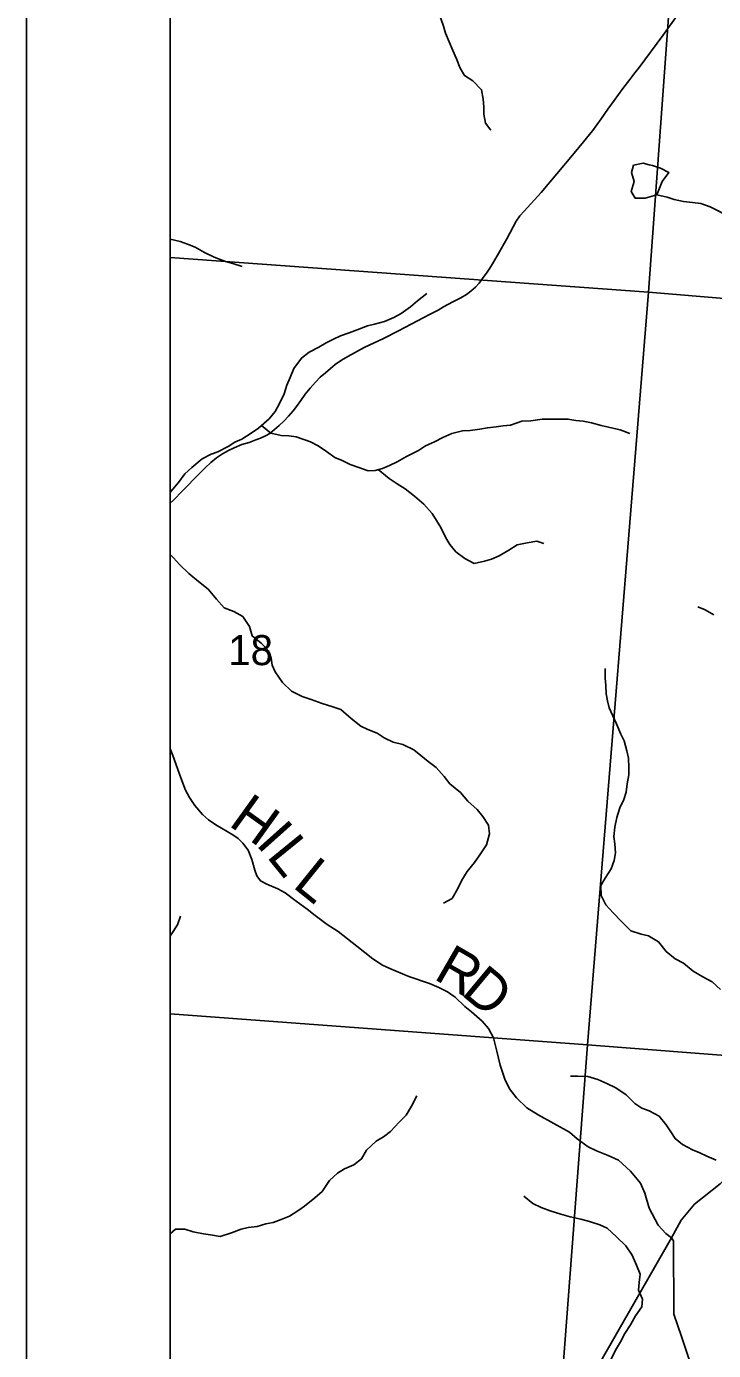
# Model space of a CAD drawing. Extents: x 0 to 42, y 0 to 22.
# Drawn here: x 2 to 2.478, y 14.957 to 15.878 of the extents above; entities that cross this region are included whole.
import ezdxf

# ---------------------------------------------------------------- set-up
doc = ezdxf.new("R2010")
doc.units = 0
for name, color, linetype in [('GM_X_Minor_Lake', 7, 'Continuous'), ('GM_X_Minor_River', 7, 'Continuous'), ('GM_X_Section', 7, 'Continuous'), ('GM_X_Section_Text', 7, 'Continuous'), ('GM_X_State_Route', 7, 'Continuous'), ('GM_X_Township_Road', 7, 'Continuous'), ('GM_X_Township_Road_Text', 7, 'Continuous'), ('GM_X_Unincorporated', 7, 'Continuous'), ('SH_Cut_Line', 7, 'Continuous'), ('SH_Data', 7, 'Continuous')]:
    doc.layers.add(name, color=color, linetype=linetype)

msp = doc.modelspace()

# ---------------------------------------------------------------- linework, layer by layer
at = {"layer": 'GM_X_Minor_Lake'}
for points in [[(2.43328, 15.78219), (2.42907, 15.78317), (2.42245, 15.78187), (2.4211, 15.77676), (2.42297, 15.7705), (2.42087, 15.76368), (2.4235, 15.75893), (2.4305, 15.75891), (2.43864, 15.76115)], [(2.43864, 15.76115), (2.44245, 15.77061), (2.44702, 15.77685), (2.44116, 15.7799), (2.43569, 15.78163), (2.43328, 15.78219)]]:
    msp.add_lwpolyline(points, dxfattribs=at)
at = {"layer": 'GM_X_Minor_River'}
for points in [[(2.27116, 15.92349), (2.27428, 15.9183), (2.27766, 15.91185), (2.28047, 15.90502), (2.28291, 15.89856), (2.28609, 15.89078), (2.28834, 15.88395), (2.29021, 15.87864), (2.29171, 15.87371), (2.29677, 15.86175), (2.29921, 15.85586), (2.30183, 15.84941), (2.30484, 15.84428), (2.31069, 15.84066), (2.31672, 15.83438), (2.31783, 15.82794), (2.31819, 15.82244), (2.31836, 15.81732), (2.31947, 15.81106), (2.32323, 15.80631)], [(2.5144, 15.73699), (2.5093, 15.7389), (2.50382, 15.74119), (2.49815, 15.74292), (2.49324, 15.74408), (2.48833, 15.74618), (2.48267, 15.74942), (2.47568, 15.75286), (2.46926, 15.75516), (2.46359, 15.75594), (2.45716, 15.75672), (2.45073, 15.75807), (2.44582, 15.75961), (2.43864, 15.76115)], [(2.1, 15.73038), (2.10694, 15.72866), (2.11204, 15.72694), (2.11733, 15.72483), (2.12393, 15.72121), (2.13054, 15.71777), (2.13847, 15.7149), (2.14358, 15.71355), (2.15019, 15.71144)], [(2.1, 15.55412), (2.10043, 15.55471), (2.10575, 15.56094), (2.11031, 15.56718), (2.11506, 15.57152), (2.12227, 15.57756), (2.12852, 15.58076), (2.13326, 15.58245), (2.14027, 15.58621), (2.14501, 15.58903), (2.14993, 15.59129), (2.15638, 15.59544), (2.1615, 15.59883), (2.1689, 15.60543), (2.17308, 15.61034), (2.17613, 15.61602), (2.17937, 15.62264), (2.18128, 15.62889), (2.18357, 15.63419), (2.18605, 15.64043), (2.19138, 15.64761), (2.19669, 15.65176), (2.20351, 15.65534), (2.20863, 15.65835), (2.21356, 15.6608), (2.21848, 15.66305), (2.22454, 15.66511), (2.23003, 15.66718), (2.23723, 15.66999), (2.24216, 15.6713), (2.24916, 15.67317), (2.2556, 15.6758), (2.26072, 15.67862), (2.26736, 15.68333), (2.2721, 15.68749), (2.27855, 15.69258)], [(2.1636, 15.6007), (2.17, 15.59539), (2.17718, 15.59365), (2.18247, 15.59344), (2.18777, 15.59285), (2.19759, 15.58941), (2.20307, 15.58654), (2.20873, 15.58254), (2.21457, 15.57835), (2.21967, 15.57625), (2.22534, 15.57357), (2.23119, 15.57147), (2.23781, 15.56917), (2.24272, 15.56934), (2.24765, 15.57084), (2.25257, 15.5729), (2.25788, 15.57535), (2.26451, 15.57911), (2.27285, 15.58325), (2.27778, 15.58645), (2.28384, 15.58946), (2.28972, 15.59247), (2.29597, 15.5951), (2.30354, 15.59697), (2.30884, 15.59714), (2.31546, 15.59806), (2.32077, 15.59918), (2.32682, 15.59972), (2.33174, 15.60046), (2.33685, 15.60101), (2.34461, 15.60364), (2.35105, 15.60399), (2.35881, 15.6051), (2.37148, 15.60505), (2.37678, 15.60522), (2.38226, 15.60425), (2.38736, 15.60367), (2.39322, 15.60251), (2.40002, 15.60077), (2.41325, 15.59769), (2.41986, 15.5952)], [(2.24484, 15.56998), (2.25235, 15.56381), (2.25801, 15.56018), (2.26348, 15.55656), (2.27009, 15.55161), (2.2765, 15.5459), (2.28234, 15.53944), (2.28534, 15.53469), (2.28835, 15.52975), (2.29192, 15.52253), (2.29455, 15.51778), (2.29888, 15.51284), (2.30511, 15.50808), (2.31153, 15.50464), (2.31872, 15.50632), (2.32364, 15.50763), (2.32895, 15.51007), (2.33558, 15.51403), (2.34146, 15.51761), (2.34846, 15.5191), (2.35509, 15.52021), (2.36, 15.51848)], [(2.1, 15.51086), (2.10234, 15.50865), (2.10648, 15.50389), (2.11308, 15.49781), (2.11968, 15.4921), (2.12647, 15.48676), (2.13231, 15.47992), (2.13758, 15.47383), (2.14438, 15.47116), (2.15061, 15.46772), (2.15512, 15.46088), (2.15699, 15.45424), (2.16322, 15.44929), (2.16849, 15.44396), (2.17018, 15.43884), (2.17091, 15.43391), (2.17317, 15.42916), (2.17825, 15.42175), (2.18447, 15.41586), (2.19183, 15.41204), (2.19806, 15.40993), (2.20581, 15.40725), (2.21318, 15.40495), (2.21884, 15.40303), (2.22601, 15.39675), (2.23261, 15.39142), (2.23752, 15.38912), (2.24394, 15.38664), (2.24885, 15.38339), (2.25527, 15.38034), (2.26188, 15.3788), (2.26962, 15.37498), (2.27452, 15.37098), (2.27962, 15.36679), (2.28509, 15.3626), (2.29074, 15.35651), (2.29469, 15.35138), (2.30205, 15.34529), (2.30713, 15.33921), (2.31373, 15.3335), (2.31749, 15.32855), (2.32163, 15.32266), (2.32218, 15.3166), (2.32007, 15.30883), (2.3155, 15.30184), (2.31189, 15.29655), (2.30676, 15.29031), (2.30296, 15.28426), (2.3001, 15.27858), (2.29629, 15.27159), (2.29022, 15.26839)], [(2.47841, 15.46895), (2.47237, 15.47238), (2.46727, 15.47449)], [(2.48293, 15.20815), (2.47709, 15.21347), (2.47067, 15.2171), (2.46407, 15.22092), (2.45728, 15.22663), (2.45143, 15.22949), (2.4452, 15.23463), (2.43993, 15.24148), (2.43295, 15.24548), (2.42766, 15.24664), (2.42067, 15.24913), (2.41388, 15.25579), (2.40823, 15.2615), (2.40314, 15.2672), (2.39995, 15.27366), (2.3996, 15.28048), (2.40264, 15.28559), (2.40683, 15.29221), (2.40893, 15.29788), (2.4099, 15.30338), (2.40954, 15.30963), (2.4088, 15.31475), (2.40939, 15.32119), (2.41074, 15.32801), (2.41304, 15.33464), (2.41571, 15.34031), (2.41724, 15.34561), (2.41802, 15.35129), (2.41918, 15.35755), (2.41919, 15.36266), (2.41884, 15.3693), (2.41791, 15.37423), (2.41605, 15.38125), (2.41361, 15.38599), (2.41042, 15.39359), (2.40554, 15.40422), (2.40423, 15.40915), (2.4035, 15.41389), (2.40314, 15.41977), (2.40278, 15.42489), (2.40262, 15.43171)], [(2.1, 15.24528), (2.1008, 15.24655), (2.10499, 15.25316), (2.10709, 15.25922)], [(2.47985, 15.08932), (2.47343, 15.09219), (2.46852, 15.09448), (2.46342, 15.09659), (2.45643, 15.10022), (2.45134, 15.10441), (2.44833, 15.10916), (2.44513, 15.11391), (2.44024, 15.11999), (2.43344, 15.12381), (2.42815, 15.12572), (2.42325, 15.12896), (2.41741, 15.13486), (2.41024, 15.13981), (2.40382, 15.14268), (2.39759, 15.14555), (2.39059, 15.14766), (2.38379, 15.14787), (2.37868, 15.14789)], [(2.1, 15.03819), (2.10364, 15.04147), (2.11026, 15.04145), (2.11593, 15.03953), (2.12311, 15.03818), (2.12803, 15.0374), (2.13483, 15.03624), (2.14259, 15.03886), (2.14941, 15.0413), (2.15434, 15.04261), (2.16058, 15.04334), (2.16664, 15.04503), (2.17175, 15.04614), (2.17724, 15.04821), (2.18293, 15.05046), (2.1888, 15.05404), (2.19354, 15.05743), (2.20056, 15.06309), (2.20569, 15.06762), (2.21082, 15.07518), (2.21633, 15.08047), (2.22126, 15.08329), (2.2277, 15.08611), (2.2332, 15.09026), (2.23662, 15.09631), (2.24327, 15.10254), (2.24839, 15.10556), (2.25332, 15.10933), (2.2594, 15.11575), (2.26414, 15.12066), (2.26795, 15.1269), (2.27157, 15.13408)], [(2.4067, 14.95049), (2.40994, 14.9573), (2.41337, 14.96297), (2.41641, 14.96884), (2.42041, 14.97489), (2.42384, 14.98113), (2.42821, 14.98737), (2.42861, 14.99267), (2.42598, 14.99894), (2.42638, 15.00424), (2.42697, 15.01011), (2.42453, 15.01638), (2.42153, 15.0234), (2.41721, 15.02986), (2.41061, 15.03614), (2.4042, 15.04204), (2.39891, 15.04434), (2.39192, 15.04664), (2.38588, 15.04837), (2.37832, 15.04991), (2.37189, 15.05183), (2.36434, 15.05413), (2.35829, 15.05643), (2.35244, 15.0593), (2.34603, 15.06425)]]:
    msp.add_lwpolyline(points, dxfattribs=at)
at = {"layer": 'GM_X_Section'}
for points in [[(2.46933, 16.19453), (2.98825, 16.15388), (2.9429, 15.65088), (2.43288, 15.69341)], [(2.9429, 15.65088), (2.89713, 15.13046), (2.39051, 15.16957), (2.43288, 15.69341)], [(2.39051, 15.16957), (2.89713, 15.13046), (2.85743, 14.61911), (2.35157, 14.65861)]]:
    msp.add_lwpolyline(points, close=True, dxfattribs=at)
at = {"layer": 'GM_X_State_Route'}
msp.add_lwpolyline([(2.39873, 14.948), (2.44897, 15.03541), (2.45555, 15.04762), (2.4649, 15.05887), (2.48277, 15.07298), (2.49412, 15.084), (2.53744, 15.14821), (2.55144, 15.15961), (2.63013, 15.20425), (2.70391, 15.25402), (2.76009, 15.27435), (2.80169, 15.30274), (2.85317, 15.34408), (2.91664, 15.37359), (2.93772, 15.38339), (2.96629, 15.40998), (3.08666, 15.49089), (3.09434, 15.49511), (3.1583, 15.53024), (3.23643, 15.54277), (3.28467, 15.57114), (3.3075, 15.58456)], dxfattribs=at)
at = {"layer": 'GM_X_Township_Road'}
for points in [[(2.1, 16.7767), (2.1, 14.1), (4.80642, 14.1), (4.86241, 14.74155), (4.87577, 14.903), (4.88082, 14.9641), (4.90774, 15.22465), (4.90782, 15.22542), (4.91025, 15.24876), (4.91234, 15.26666), (4.91693, 15.30071), (4.92061, 15.33827), (4.92229, 15.35537), (4.9225, 15.35759), (4.92364, 15.36537), (4.92223, 15.37611), (4.92602, 15.41635), (4.9302, 15.46506), (4.93268, 15.49943), (4.95383, 15.74551), (4.96357, 15.8483), (4.97611, 15.98164)], [(2.1, 15.54658), (2.10231, 15.54872), (2.1086, 15.55527), (2.12026, 15.56702), (2.12427, 15.57131), (2.12836, 15.57504), (2.13228, 15.57823), (2.13647, 15.58105), (2.14066, 15.58333), (2.14458, 15.58515), (2.14995, 15.58743), (2.15487, 15.58898), (2.15952, 15.59071), (2.16289, 15.59189), (2.16626, 15.59344), (2.16936, 15.59517), (2.17254, 15.59791), (2.17591, 15.60082), (2.17919, 15.60383), (2.18238, 15.6072), (2.18548, 15.61084), (2.18785, 15.6139), (2.19104, 15.61804), (2.19395, 15.62241), (2.19732, 15.62678), (2.20106, 15.63079), (2.20434, 15.63425), (2.20798, 15.63735), (2.21162, 15.64035), (2.21481, 15.64327), (2.21918, 15.64609), (2.22374, 15.64873), (2.23503, 15.65511), (2.24851, 15.66131), (2.25899, 15.66668), (2.27211, 15.6736), (2.28085, 15.67825), (2.28641, 15.68107), (2.29024, 15.68335), (2.29679, 15.68672), (2.30226, 15.68954), (2.30627, 15.69191), (2.30927, 15.69428), (2.31237, 15.69692), (2.31501, 15.69984), (2.31793, 15.70366), (2.32002, 15.70667), (2.32248, 15.71013), (2.32503, 15.71441), (2.3284, 15.72052), (2.33423, 15.73053), (2.3407, 15.74292), (2.34334, 15.74657), (2.34635, 15.74985), (2.35819, 15.76278), (2.37996, 15.78874), (2.38769, 15.79815), (2.39381, 15.80587), (2.39992, 15.81425), (2.40453, 15.82089), (2.40893, 15.82696), (2.41502, 15.83527), (2.41988, 15.84158), (2.4234, 15.84621), (2.42635, 15.84992), (2.44276, 15.87215), (2.45407, 15.88776)], [(2.46189, 14.9486), (2.45586, 14.96659), (2.45047, 14.98221), (2.45023, 15.03327), (2.44897, 15.03541), (2.4449, 15.0384), (2.43961, 15.04413), (2.43343, 15.05602), (2.43026, 15.06649), (2.4274, 15.0733), (2.42043, 15.08171), (2.41202, 15.08932), (2.40486, 15.09276), (2.39664, 15.09582), (2.39086, 15.09869), (2.38332, 15.10438), (2.37793, 15.10898), (2.35605, 15.12087), (2.34812, 15.12595), (2.34099, 15.13276), (2.33623, 15.13895), (2.3329, 15.14577), (2.32973, 15.1556), (2.32735, 15.16527), (2.32497, 15.17462), (2.32164, 15.18097), (2.31704, 15.18604), (2.30959, 15.1927), (2.30499, 15.19635), (2.29833, 15.20285), (2.29294, 15.20665), (2.28692, 15.20966), (2.28042, 15.21236), (2.26615, 15.21728), (2.25283, 15.22282), (2.24775, 15.2252), (2.24094, 15.22948), (2.22984, 15.23836), (2.21684, 15.24851), (2.20922, 15.25343), (2.20098, 15.25961), (2.19543, 15.26421), (2.18766, 15.26976), (2.18005, 15.27547), (2.17482, 15.27832), (2.16736, 15.28149), (2.16293, 15.28371), (2.16023, 15.2872), (2.15896, 15.29116), (2.15674, 15.29862), (2.1542, 15.30512), (2.15056, 15.31003), (2.14723, 15.3132), (2.14358, 15.31574), (2.13169, 15.32288), (2.12677, 15.32636), (2.12249, 15.33001), (2.11726, 15.33635), (2.11345, 15.34174), (2.11076, 15.34682), (2.10743, 15.35554), (2.10188, 15.37108), (2.1, 15.37571)]]:
    msp.add_lwpolyline(points, dxfattribs=at)
at = {"layer": 'GM_X_Unincorporated'}
for points in [[(2.1, 16.22845), (2.1, 15.71754), (2.43288, 15.69341), (2.46933, 16.19453)], [(2.1, 15.71754), (2.1, 15.19123), (2.39051, 15.16957), (2.43288, 15.69341)], [(2.1, 15.19123), (2.1, 14.68252), (2.35157, 14.65861), (2.39051, 15.16957)]]:
    msp.add_lwpolyline(points, close=True, dxfattribs=at)
at = {"layer": 'SH_Cut_Line'}
msp.add_lwpolyline([(2.1, 20.9), (2.1, 14.1), (8.05023, 14.1), (8.06868, 14.30702), (8.08338, 14.51358), (8.1512, 15.24132), (8.15761, 15.31908), (8.1628, 15.37905), (8.16837, 15.44612), (8.16945, 15.45935), (8.16983, 15.46634), (8.17227, 15.49063), (8.24231, 16.32059)], dxfattribs=at)
at = {"layer": 'SH_Data'}
for p, q in [((2, 21), (2, 14)), ((2.1, 20.9), (2.1, 14.1))]:
    msp.add_line(p, q, dxfattribs=at)

# ---------------------------------------------------------------- texts
at = {"layer": 'GM_X_Section_Text'}
msp.add_text('18', height=0.020928, rotation=0.00001, dxfattribs=at).set_placement((2.14044, 15.43393))
at = {"layer": 'GM_X_Township_Road_Text'}
for s, rotation, p in [('H', 324.29294, (2.13991, 15.32281)), ('I', 311.7418, (2.15899, 15.30932)), ('L', 309.11964, (2.16654, 15.30087)), ('L', 321.0598, (2.18444, 15.27991)), ('R', 329.98209, (2.28258, 15.21599)), ('D', 320.22848, (2.30173, 15.20505))]:
    msp.add_text(s, height=0.02841, rotation=rotation, dxfattribs=at).set_placement(p)

doc.saveas('drawing.dxf')
